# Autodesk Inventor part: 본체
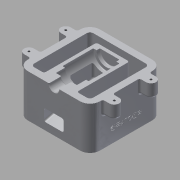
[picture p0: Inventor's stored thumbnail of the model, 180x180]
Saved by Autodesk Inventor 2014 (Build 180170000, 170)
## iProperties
Created: 2018-01
Part Number: 본체
Material: 알루미늄 6061
Document SubType Name: Modeling
Designer: user
Density: 2.71 g/cm^3
Appearance: 알루미늄 - 평지
Mass: 998.995 g
Surface Area: 834.574 cm^2
Volume: 368.633 cm^3
Author: user
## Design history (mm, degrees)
sketch "스케치1"
  geometry: L1 (-40, 55)-(40, 55); L2 (55, 40)-(55, -40); L3 (40, -55)-(-40, -55); L4 (-55, -40)-(-55, 40); L5 (40, 45)-(-40, 45); L6 (-45, 40)-(-45, -40); L7 (-40, -45)-(40, -45); L8 (45, -40)-(45, 40); A1 r 15 centre (-40, 40) between (-40, 55) and (-55, 40); A2 r 15 centre (40, 40) between (55, 40) and (40, 55); A3 r 15 centre (40, -40) between (40, -55) and (55, -40); A4 r 15 centre (-40, -40) between (-55, -40) and (-40, -55); A5 r 5 centre (-40, 40) between (-40, 45) and (-45, 40); A6 r 5 centre (-40, -40) between (-45, -40) and (-40, -45); A7 r 5 centre (40, -40) between (40, -45) and (45, -40); A8 r 5 centre (40, 40) between (45, 40) and (40, 45); 6 further points
  constraints: 16 end point, 16 point on circle, 8 centre point, 8 tangent, 6 point on line, 4 parallel, 3 equal radius, 2 midpoint, 2 perpendicular, 1 horizontal, 1 horizontal alignment, 1 vertical alignment, 7 other
  dimensions: "d0" = 110 distance of point (-55, 55) point (55, 55); "d1" = 110 distance of point (55, 55) point (55, -55); "d2" = 15 radius of A1; "d3" = 10 distance between parallel lines of L1 L5
extrude "돌출1" new body sketch "스케치1" distance "d4" = 65; taper "d5" = 0 deg
sketch "스케치2"
  geometry: L1 (-65, -20.5)-(-55, -20.5); L2 (-65, -35.5)-(-55, -35.5); L3 (-55, 40)-(-55, -40) reference; A1 r 7.5 centre (-65, -28) between (-65, -20.5) and (-65, -35.5); 1 further point
  constraints: 4 end point, 2 point on circle, 2 point on line, 2 tangent, 1 centre point, 1 horizontal, 1 parallel
  dimensions: "d6" = 15 diameter of A1; "d7" = 10 distance from line of L3 A1.centre; "d8" = 28 vertical distance of A1.centre point (0, 0)
extrude "돌출2" join sketch "스케치2" distance "d9" = 20; taper "d10" = 0 deg
hole "구멍1" diameter "d16" = 3.242; stored, may be unused: countersink angle "d20" = 90 deg, drill point angle "d22" = 118 deg; dims "d17" = 9, "d18" = 4, "d19" = 2, "d21" = 11, "d23" = 10, "d24" = 10
sketch "스케치3"
  geometry: L1 (55, 65)-(55, 0) reference; L2 (55, 0)-(45, 0) reference; L3 (45, 0)-(45, 65) reference; L4 (45, 65)-(55, 65) reference; L5 (-55, 0)-(-55, 65) reference; L6 (-55, 65)-(-45, 65) reference; L7 (-45, 65)-(-45, 0) reference; L8 (-45, 0)-(-55, 0) reference; L9 (-45, 8.564)-(35, 30); L10 (35, 30)-(35, 65); L11 (35, 65)-(-45, 65); 1 further point
  constraints: 6 end point, 2 perpendicular, 1 horizontal alignment, 1 point on line
  dimensions: "d25" = 20 distance from line of L1.start L10; "d26" = 105 deg angle of L7 L9; "d27" = 30 vertical distance of L1.end L9.end
extrude "돌출3" join sketch "스케치3" stored distance "d28" = 50; taper "d29" = 0 deg
sketch "스케치4"
  geometry: L1 (55, 65)-(55, 0) reference; L2 (55, 0)-(45, 0) reference; L3 (45, 0)-(45, 65) reference; L4 (45, 65)-(55, 65) reference; L5 (-55, 0)-(-55, 65) reference; L6 (-55, 65)-(35, 65) reference; L7 (35, 65)-(35, 30) reference; L8 (35, 30)-(-45, 8.564) reference; L9 (-45, 8.564)-(-45, 0) reference; L10 (-45, 0)-(-55, 0) reference; L11 (-55, 57.5)-(-36, 57.5); L12 (-36, 57.5)-(-36, 49); L13 (-36, 49)-(-22, 49); L14 (-22, 49)-(-22, 45); L15 (-22, 45)-(25, 45); L16 (25, 45)-(25, 50); L17 (25, 50)-(30, 50); L18 (30, 50)-(30, 65); 1 further point
  constraints: 16 end point, 5 parallel, 3 perpendicular, 2 point on line
  dimensions: "d30" = 7.5 distance between parallel lines of L6 L11; "d31" = 16 distance between parallel lines of L6 L13; "d32" = 20 distance between parallel lines of L6 L15; "d33" = 15 distance between parallel lines of L6 L17; "d34" = 19 distance of L11.start L11.end; "d35" = 14 distance of L12.end L13.end; "d36" = 47 distance of L14.end L15.end; "d37" = 5 distance of L16.end L17.end
revolve "회전1" sketch "스케치4" stored, may be unused: angle "d38" = 90 deg
sketch "스케치6"
  geometry: L1 (35, 30)-(-45, 8.564) reference; L2 (-55, 0)-(-55, 65) reference; L3 (20, 31.157)-(-55, 11.061); L4 (25, 50)-(25, 65) reference; 1 further point
  constraints: 2 end point, 1 parallel, 1 point on line
  dimensions: "d48" = 5 distance between parallel lines of L1 L3; "d68" = 5 distance from line of L3.start L4
sketch "스케치8"
  geometry: L1 (25, 29.061)-(55, 29.061); L2 (55, 29.061)-(55, 11.061); L3 (55, 11.061)-(25, 11.061); L4 (25, 11.061)-(25, 29.061); L5 (0, 0)-(80, 0) reference; 4 further points
  constraints: 8 end point, 3 midpoint, 2 parallel, 1 horizontal, 1 perpendicular, 1 vertical alignment
  dimensions: "d49" = 18 distance of L1.end L2.end; "d50" = 30 distance of L1.start L1.end
feature "스윕1" sketch "스케치6", "스케치8" dims "d51" = 0
sketch "스케치7"
  geometry: L1 (-20, -22)-(-20, 25) reference; L2 (20, -22)-(-20, -22) reference; L3 (20, 25)-(20, -22) reference; L4 (20, 25)-(-20, 25) reference; L5 (-15, 20)-(15, 20); L6 (15, 20)-(15, -17); L7 (15, -17)-(-15, -17); L8 (-15, -17)-(-15, 20); 2 further points
  constraints: 8 end point, 2 parallel, 1 horizontal, 1 midpoint, 1 perpendicular, 1 vertical alignment
  dimensions: "d43" = 5 distance between parallel lines of L4 L5; "d44" = 5 distance between parallel lines of L2 L7; "d45" = 30 distance between parallel lines of L6 L8
extrude "돌출5" cut sketch "스케치7" stored distance "d52" = 35; taper "d53" = 0 deg
fillet "모깎기1" dims "d54" = 1
fillet "모깎기11" dims "d67" = 3
fillet "모깎기2" dims "d55" = 3
chamfer "모따기1" distance "d56" = 1; stored, may be unused: second distance "d57" = 2, angle "d58" = 45 deg
fillet "모깎기3" dims "d59" = 3
fillet "모깎기4" dims "d60" = 3
fillet "모깎기12" dims "d73" = 3
fillet "모깎기5" dims "d61" = 3
fillet "모깎기7" dims "d63" = 3
sketch "스케치9"
  geometry: L1 (0, -15)-(-65, -15) reference; 2 further points
  constraints: 1 other
  dimensions: "d69" = 20 distance of point (0, 40) point (-20, 40); "d70" = 55 distance from line of L1 point (-20, 40)
feature "엠보싱1" sketch "스케치9" dims "d0" = 110, "d1" = 110, "d2" = 15, "d3" = 10, "d71" = 0.5, "d72" = 0
node "솔리드1"
pattern_linear "직사각형 패턴1" dims "d13" = 56
mirror "대칭1"
node "투영된 루프2"
node "절단 모서리 투영1"
node "절단 모서리 투영2"
